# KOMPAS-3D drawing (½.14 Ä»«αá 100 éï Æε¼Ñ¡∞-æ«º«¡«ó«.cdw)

Views: Вид 1, Вид 2, Вид 3, Вид 4
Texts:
  Текст на чертеже
  Размерные надписи
  Шероховатость
  Линия-выноска #1
  Линия-выноска #2
  Линия-выноска #3
  Отклонения формы и база
  Заголовок таблицы
  Ячейка таблицы
  Стрелка вида
  Обозначение изменения
  Фигурная скобка
  Номер узла
  Марка координационной оси
  VRCB
  Выносная надпись
  Обозначение узла
  Марка/позиционное обозначение с линией-выноской
  Марка/позиционное обозначение на линии
  Марка/позиционное обозначение без линии-выноски
  Лит-Масса-Масштаб
  Материал-Предприятие
  Normal
  ООббыыччнныыйй
  Definition Term
  Definition List
  Address
  Blockquote
  Preformatted
  Courier New
  z-Bottom of Form
  z-Top of Form
  Title Specification
  Body Specification ( left align )
  Body Specificaton ( centered )
  Без имени
  SPEC
  Txt
  Body Text
  heading 1
  Знак Знак Знак Знак Знак Знак
  Verdana
  Simplex
  TXT
  txt
  MS Sans Serif
  Additional DXF text style 0
  Обычный
  Термин
  Список определений
  Адрес
  Цитаты
  Форматированный
  Z-конец формы
  Z-начало формы
  ТекстШаг1
  Title
  Денис
  header
  heading 2
  AGOpus
  footer
  NormalParagraphStyle
  Body Text 3
  ссылки
  Подпись в квадратике
  табл
  цепи
  Маркировка
  клеммы, контакты
  тексты табл
  Тексты. 3,2
  ЗОНА_привяз
  текст переноса
  ТТееррммиинн
  ССппииссоокк ооппррееддееллеенниийй
  ААддрреесс
  ЦЦииттааттыы
  ФФооррммааттиирроовваанннныыйй
  Z-ккооннеецц ффооррммыы
  Z-ннааччааллоо ффооррммыы
  GOST 2.304 type A
  rustxt
  heading 8
  heading 3
  heading 6
  heading 7
  russ
  Абзац Знак
  heading 4
  heading 5
  heading 9
  HeliosLight
  Pa3
  Pa1
  Три с половиной
  style2
  Шрифт 2.5
  Заголовки
  RUSTXT
  Table Contents
  Table Heading
  ГОСТ_МНЕ
  ESK - Обозначение
  маркировка
  ISOCP
  ROMANS
  SIMPLEX
  Обычный (веб)
  Текст 3,5
  Tahoma
  CNBNDG+TimesNewRoman
  Subtitle
  ISOCPEUR
  FR5
  romans
  Подписи
  Примечание - примечания см. 16/01-ПОС, л.10.
  Схема монтажа ВЧ-заградителя на опору №100.
  Отпайка ВЛ-110 кВ Тюмень-Сазоново на ПС Борки
  Кран КС-35719-1-02
  GOST2.303 4_RGB_173_173_173_SC_0.04_THICK_0.13
  CONTINUOUS_RGB_0_0_0_THICK_0.13
  POLYLINE_STYLE_0.18_RGB_0_0_0
  CONTINUOUS_RGB_173_173_173_THICK_0.13
  CONTINUOUS_RGB_0_0_0_THICK_0.18
  ACAD_ISO04W100_RGB_255_0_0_SC_1_THICK_0.13
  Автомобильный кран КС-35714
  Перезавод ВЛ на ПС Тюмень. Реконструкция устройств
  РЗ и ПА на обратных концах отходящих ВЛ,
  ВОЛС Тюменского ТПО
  ВЛ-110 кВ Тюмень - Созоново
  Ромин
  Подвеска ВЧ-заградителя
  на опоре №100
  Политова
  Разраб.
  Микрюков
  Ведомость эскизного проекта
  Нов.
  ГИП
  Матвеев
Dimensions and other numbers on the sheet: 16/01-ПОС; 7; 3,2_; 3.5; 2.5; 2,5; 1,8; 3,2; 2,5 (контакты, клеммы); 3,2 (надписи); 3,2 (Зоны); 5; 2,5_01; 2,5_3; 3,5_01; 3,5_tabl; 5_заголовок; 2,3_; 3,2_зона не привяз; 3,5; 3.2 маркировка; 3,2 элементы; 3,2 линия; 3,2 таблица; 2,5 грязносинь; 2.5 курсив; 2.5_Э5_надписи; 2.5_Э5_ссылки; 2.5_кабель; 3.2; 2.5 надписи; 3 и 5; 5,0_белый_подчёркнутый; 3.2 фиол; 3.2 (текст); 25300; 13700; 6100; 4400; 3600; 12; 4; 1; 05.14; 16/01-03-091-ЭП-; 14; 3; 253-14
